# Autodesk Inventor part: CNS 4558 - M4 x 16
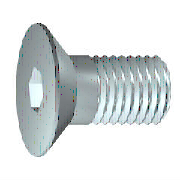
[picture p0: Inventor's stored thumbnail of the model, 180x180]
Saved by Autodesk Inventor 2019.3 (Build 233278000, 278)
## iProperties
Created: 2018-01
Part Number: CNS 4558 - M4 x 16
Material: Ocel, měkká
Description: Šroub se zápustnou hlavou
Document SubType Name: Modeling
Standard: CNS 4558
Designer: B-hon
Standards Organization: CNS
Language: cs-CZ
Size Designation: M4 x 16
Categories: <MemberInstance><Categories><Category DisplayName="Spojovací materiál" InternalName="e4da775c-781d-43d5-af7c-5136215cf5a6" Mnemonic="FSTN"><Category DisplayName
Density: 7.85 g/cm^3
Appearance: Pololeštěná
IsCustomPart: 0
Author: B-hon
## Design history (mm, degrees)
body "Solid1"
revolve "Těleso" stored, may be unused: angle "d13" = 90 deg
sketch "Náčrt2"
  geometry: L1 (0, -5.6)-(0, 5.6) reference; L2 (-5.6, 0)-(5.6, 0) reference; L3 (1.443, 0)-(0.722, -1.25); L4 (0.722, -1.25)-(-0.722, -1.25); L5 (-0.722, -1.25)-(-1.443, 0); L6 (-1.443, 0)-(-0.722, 1.25); L7 (-0.722, 1.25)-(0.722, 1.25); L8 (0.722, 1.25)-(1.443, 0); A1 r 1.443 centre (0, 0) between (0, 1.443) and (1.443, 0) reference; 2 further points
  constraints: 12 end point, 2 coincident, 2 point on circle, 2 point on line, 12 other
extrude "Drážka" join sketch "Náčrt2" taper "d14" = 0 deg; stored distance "d30" = 10
feature "Závit" dims "d15" = 11.6 (= GEL), "d16" = 0
chamfer "Zkosení1" distance "d17" = 0.42941 (= -0.5 x SPD + 0.5 x GD); stored, may be unused: second distance "d18" = 0.42941 (= GUL), angle "d39" = 45 deg
workplane "Work Plane1"
sketch "Náčrt1"
  geometry: L1 (16, 0)-(16, 2); L2 (16, 2)-(4.4, 2); L3 (4.4, 2)-(3.971, 2); L4 (0, 4)-(0, 1.443); L5 (0, 1.443)-(1.8, 1.443); L6 (1.8, 1.443)-(2.633, 0); L7 (2.633, 0)-(16, 0); L8 (0, 4)-(0.3, 4); L9 (0.3, 4)-(2.3, 2); L10 (3.971, 2)-(2.3, 2); L11 (4.4, 2)-(2.3, 2); L12 (2.3, 2)-(2.3, 2); L13 (-3.2, 0)-(19.2, 0) reference; L14 (0, -0.8)-(0, 4.8) reference
  constraints: 24 end point, 4 collinear, 3 parallel
  dimensions: "d0" = 16 distance between parallel lines of L4 L1 (= NLG); "d1" = 11.6 distance from line of L2.end L1 (= GEL); "d2" = 1.8 distance from line of L5.end L4 (= INTI); "d3" = 4 diameter of L2 L7 (= GD); "d6" = 2.3 distance from line of L9.end L4 (= KOH); "d7" = 45 deg angle of L9 L7 (= 0.5 x SEWI); "d8" = 2.88675 diameter of L5 L7 (= 1.1547 x SW); "d9" = 60 deg angle of L6 L7; "d10" = 8 diameter of L8 L7 (= KOD); "d11" = 4 diameter of L10 L7 (= BDM); "d12" = 0.42941 distance of L3.end L2.end (= GAL)
other parameters: "NLG" = 16 [user parameter; used in 1 equation term], "INTI" = 1.8 [user parameter; used in 1 equation term], "GEL" = 11.6 [user parameter; used in 2 equation terms], "GAL" = 0.42941 (= 0.61345 x PTC) [user parameter; used in 1 equation term], "KOH" = 2.3 [user parameter; used in 1 equation term], "KOD" = 8 [user parameter; used in 1 equation term], "GUL" = 0.42941 (= 0.61345 x PTC) [user parameter; used in 1 equation term], "SPD" = 3.14117 (= NND - 1.2269 x PTC) [user parameter; used in 1 equation term], "BDM" = 4 (= NND) [user parameter; used in 1 equation term], "GD" = 4 (= NND) [user parameter; used in 2 equation terms], "SEWI" = 90 deg [user parameter; used in 1 equation term], "d20" = 0, "SW" = 2.5 [user parameter; used in 2 equation terms], "d43" = 0, "d44" = 0, "TOA" = 30 deg [user parameter], "GD1" = 3.14117 (= THREADDIA - 1.2269 x PTC) [user parameter], "EPV" = 4.3 [user parameter], "THREADDIA" = 4 [user parameter; used in 1 equation term], "TPU" = 14.28571 (computed from PTC) [user parameter], "PTC" = 0.7 [user parameter; used in 5 equation terms], "NND" = 4 [user parameter; used in 3 equation terms], "E0" = 2.8875 (= 1.155 x SW) [user parameter]
